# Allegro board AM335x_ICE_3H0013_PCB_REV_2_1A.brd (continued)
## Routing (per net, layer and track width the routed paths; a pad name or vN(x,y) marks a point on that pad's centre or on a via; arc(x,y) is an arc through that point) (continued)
GND_EARTH: length 5.8
  TOP w0.381: S1.3 v1(0.89,20.83)
  TOP w0.762: v2(2.37,5.39) 2.41,5.39 3.25,4.55 J13.S1 ; J13.S2 9.45,4.77 v2(8.89,5.33)
  BOTTOM w0.762: J16.11 29.09,13.59 28.84,13.84
  vias: v2(30.1,1.02)
GND_OSC0: length 16.1
  TOP w0.203: U14.V11 37.85,51.57 v1(37.85,53.34)
  LYR4 w0.381: v1(34.89,53.63) 35.6,53.63 35.74,53.77 37.16,53.77 37.59,53.34 v1(37.85,53.34) 38.22,53.72 38.22,53.73 40.87,56.37 v1(40.87,57.76)
  BOTTOM w0.381: v1(34.89,53.63) 35.46,54.19 35.46,55.41 35.1,55.77 35.04,55.77 C99.2 ; C100.2 40.89,57.74 v1(40.87,57.76) ; v1(37.85,53.34) 37.92,53.26 37.92,53.24 38.35,52.81 C106.2
GND_OSC1: length 13.5
  TOP w0.381: U14.A5 42.97,35.26 43.69,34.54 43.69,33.66 44.11,33.24 44.11,31.88 43.94,31.72 43.94,29.96 44.52,29.39 45.01,29.39 45.4,29.78 45.4,30.04 C40.1 45.91,30.23 v1(46.2,29.93) 46.2,29.01 45.59,28.4 C42.1
GNDA_ADC: length 77.7
  TOP w0.305: v1(40.97,40.45) U14.E8 ; v1(40.17,37.25) U14.A9
  TOP w0.381: C36.2 40.39,32.17 40.49,32.07 v1(40.49,31.65) ; C36.2 C35.2 C34.2 ; C36.2 40.89,32.77 41.15,33.02 41.15,34.8 40.17,35.78 v1(40.17,37.25) ; C34.2 C33.2 ; C34.2 38.35,32.19 v1(38.19,32.02)
  LYR3 w0.508: v2(71.1,31.82) 71,31.72 v2(71,30.76)
  LYR3 w0.635: v1(38.19,32.02) 38.1,31.93 38.1,31.22 39.28,30.05 40.06,30.05 40.49,30.48 v1(40.49,31.65) 40.78,31.94 41.67,31.94 42.68,30.94 43.42,30.94 45.67,28.69 46.45,27.9 46.45,27.89 47.07,27.27 60.96,27.27 61.6,27.9 63.04,27.9 63.88,27.06 65.79,27.06 66.74,28.01 68.25,28.01 v2(71,30.76)
  LYR4 w0.635: v2(71.1,31.82) 71.03,31.9 71.03,33.3 71.38,33.66 71.38,38.06 71.8,38.48 71.8,47.17 J14.38 J14.40
  BOTTOM w0.635: FB11.1 37.85,31.75 38.1,32 38.17,32 v1(38.19,32.02)
  BOTTOM w0.762: J14.39 J14.40
GNDPROFI: length 40.1
  TOP w0.635: v1(10.79,58.67) 11.7,59.58 L1.7 ; L1.6 v1(13.7,58.67) ; C24.2 22.35,53.72 21.99,53.36 21.23,53.36 v1(21.21,53.34) v1(20.45,53.34) ; U16.5 v2(5.84,45.09)
  LYR5_PWR w0.762: 16.76,39.12 16.76,40.01 16,40.01
  LYR5_PWR w0.889: 18.48,40.32 J8.3 18.48,41.47 ; 19.24,43.62 J7.2 19.24,44.77
  BOTTOM w0.508: C95.2 5.19,60.45 R153.1 8.13,60.45 8.26,60.33 ; v1(20.45,53.34) 20.45,52.47 C107.2 21.21,52.43 v1(21.21,53.34)
  BOTTOM w0.559: v1(8.26,58.67) 8.26,60.33 ; U28.11 v1(10.79,58.67) ; U28.15 15.88,58.93 v1(14.61,57.66) ; U28.14 v1(14.61,58.67) ; v1(20.45,53.34) 20.19,53.59 U27.4 ; 21.46,54.8 21.46,53.59 v1(21.21,53.34)
  BOTTOM w0.584: v1(11.16,36.02) C191.2 11.16,37.31 10.67,37.81 C185.2 v1(11.68,38.73) ; v1(6.6,49.78) R175.2
  BOTTOM w0.635: C98.2 v1(17.14,56.64) ; C96.2 4.05,60.56 C95.2
V3_3D: length 219.3
  TOP w0.254: U1.G4 v1(24.37,87.03) ; U11.16 45.2,62.11 C20.1 ; U9.16 34.02,65.04 C19.1 v1(34.8,65.02)
  TOP w0.305: v1(23.88,29.46) 23.63,29.71 U18.42 ; U18.31 20.27,22.5 v1(19.86,22.1) 18.92,22.1 18.77,22.25 U18.28 ; v2(32.64,74.55) C9.1 32.65,75.32 U2.32 ; v1(42.29,69.34) C15.1 41.49,69.39 U2.48 ; U18.56 17.27,33.61 17.2,33.54 17.16,33.54 16.9,33.27 v1(16.76,33.27) ; U18.20 v1(14.77,24.64) ; U3.48 57.87,71.29 58.55,70.61 C11.1 v1(59.31,69.98)
  TOP w0.381: R11.1 67.56,74.2 v2(67.31,74.46) ; C8.1 v1(72.9,72.09) ; U19.1 39.48,27.64 40.39,26.74 44.97,26.74 v2(45.09,26.61) ; U16.1 v2(18.03,37.47) ; SW1.C2 21.97,92.81 21.01,93.78 v2(20.7,93.78) ; U19.4 40.78,30.19 40.82,30.19 v1(41.36,30.73) ; v2(62.57,74.32) 62.56,74.32 62.54,74.3 R19.2 ; v2(64.14,68.71) 64.79,69.36 U10.5 v2(65.89,69.49) ; U7.5 47.39,67.32 C17.1 47.62,67.82 v2(47.12,68.33) ; U17.8 27.23,27.94 v1(27.66,28.37) ; 49.04,69.23 v1(49.8,69.23) ; 49.04,69.23 C12.1 ; 49.04,69.23 U5.5 ; R21.2 v1(47.24,74.17) ; v2(58.09,68.1) 57.99,68.2 57.91,68.2 57.78,68.33 R34.2 R33.2 R32.2 R31.2 54.36,68.21 53.97,67.82 53.97,67.79 v2(53.92,67.74) ; v2(45.72,73.41) 45.47,73.66 R18.2 ; v2(52.19,68.9) 52.62,68.9 53.01,68.52 53.15,68.52 R30.2 53.21,68.33 52.83,67.94 52.45,67.94 v2(52.2,68.2) ; v2(20.7,100.53) 20.7,101.42 21.08,101.81 SW1.C1 ; U4.8 68.91,75.48 68.9,75.49 68.9,75.63 C7.1 68.06,75.82 v1(67.98,75.9) ; U37.20 53.72,62.46 53.42,62.17 53.28,62.17 C277.1 53.09,61.59 53.47,61.21 v2(54.1,61.21) ; v1(72.85,66.56) 72.85,66.62 73.23,67.01 R25.2 ; R16.2 v2(48.01,76.96) ; U8.5 39.48,66.82 C18.1 39.5,66.93 39.37,67.06 39.37,67.33 v2(39.05,67.65) 39.11,67.65 39.11,67.57 38.48,68.21 R27.2 R28.2 R29.2 ; 6.22,63.12 v2(6.22,66.71) ; R15.2 v1(30.73,77.72) ; v2(49.53,75.91) 49.02,75.41 C10.1 49.28,75.06 49.78,75.06 50.05,75.32 U3.32 ; 50.29,17.65 50.04,17.4 50.04,17.14 v1(49.91,17.02) ; R24.2 v1(67.61,67.01)
  TOP w0.508: C20.1 v1(45.97,62.1)
  TOP w0.584: v1(13.34,52.58) 13.7,52.21 L1.3 ; L1.2 v1(11.7,52.58)
  LYR3 w0.381: v2(45.09,26.61) 45.14,26.66 45.14,27.96 43.05,30.05 42.31,30.05 41.62,30.73 v1(41.36,30.73)
  LYR4 w0.508: v2(59.99,19.61) 60.13,19.47 60.24,19.47 62.1,17.6 62.1,12.7 63.4,11.4 63.4,8.35 v2(60.44,5.39)
  LYR5_PWR w0.889: J3.1 5.77,72.72 ; J3.1 4.26,74.22 ; J3.1 5.77,74.22 ; J3.1 4.26,72.72
  BOTTOM w0.254: U26.18 19.92,74.99 19.01,74.99 19,75 16.95,75 C86.1 ; C88.1 16.93,70.57 U26.7 ; U26.31 28.36,74.97 C85.1 ; U26.42 27.65,70.57 C87.1
  BOTTOM w0.381: v2(37.14,78.94) 37.15,78.94 37.59,79.39 R129.2 ; v2(39.5,85.98) 39.62,85.85 39.8,85.85 40.01,85.64 C80.1 ; R97.2 v1(39.69,97.79) ; U38.20 46,56.66 C275.1 45.97,57.53 46.35,57.91 v2(46.99,57.91) ; C93.1 v2(6.22,66.71) ; v2(65.89,69.49) 65.86,69.47 65.15,69.47 ; C88.1 v1(16.13,70.61) ; R131.2 v1(30.73,77.72) ; C190.1 v2(18.03,37.47) ; v2(37.97,84.2) R123.1 R122.1 v2(40.58,84.77) 41.02,84.33 R121.1 R120.1 42.25,84.2 v2(42.8,84.75) ; R124.2 v2(53.85,84.33) ; R280.1 v1(60.01,96.14) ; v1(19.86,22.1) 20.27,22.5 20.27,22.55 C230.1 ; v2(54.61,84.33) R119.1 R118.1 ; J15.5 v1(72.9,72.09) ; v2(31.18,82.87) 31.18,83.77 R240.2 ; v2(60.02,85.22) 60.02,85.29 60.45,85.72 R114.1 ; R98.2 v1(40.96,97.79) ; v2(40.74,86.01) 41.02,85.73 C79.1 ; 43.81,87 v2(43.05,87) ; R94.2 v1(35.88,97.79) ; v1(24.37,87.03) 24.38,87.02 C75.1 C76.1 ; R118.1 C78.1 C77.1 57.59,85.66 57.59,85.8 57.71,85.92 57.72,85.92 v2(57.91,86.11) ; R118.1 R117.1 R116.1 v2(59.18,84.33) ; v2(18.03,98.21) C70.1 18.07,98.89 U25.8 ; J17.7 58.06,4.21 58.09,4.25 58.09,4.57 58.93,5.41 58.93,5.59 C266.1 ; R90.2 v1(57.47,97.79) ; R89.2 v1(56.2,97.79) ; C69.1 v2(20.7,100.53) ; R279.1 39.69,95.07 v1(39.69,96.14) ; R93.2 v1(61.28,97.79) ; v1(16.76,33.27) 17.02,33.53 C207.1 ; 64.14,69.47 v2(64.14,68.71) ; R111.2 v2(17.78,87.88) ; v1(4.57,24.13) 4.06,24.13 3.81,23.88 R211.2 C232.2 ; R92.2 v1(60.01,97.79) ; C86.1 v1(16.13,75.06) ; v2(62.99,77.6) R130.2 ; R101.2 v2(26.42,93.73) ; 29.59,82.93 v2(29.59,82.17) ; R95.2 v1(37.15,97.79) ; FB12.1 16.26,29.28 v1(16.26,30.11) 16.26,30.92 FB10.1 15.63,30.93 v1(15.63,30.11) 15.62,30.11 15.62,29.27 FB12.1
  BOTTOM w0.508: C219.1 R200.2 27.59,28.45 v1(27.66,28.37) ; R205.2 v1(11.94,24.64) ; v2(34.04,62.99) 34.04,63.88 33.77,64.15 C92.1 33.27,64.15 33.02,63.9 v2(33.02,62.99) ; C231.1 14.47,23.88 14.47,24.34 v1(14.77,24.64) ; v2(49.75,78.87) 49.73,78.86 R241.2 ; C85.1 v2(28.45,74.3) ; U31.1 61.09,21.72 60.71,21.34 C236.1 C238.1 60.17,19.3 59.99,19.48 v2(59.99,19.61) ; v1(9.91,21.34) 9.78,21.46 9.78,22.23 R210.2 9.08,22.35 9.02,22.29 U33.6 ; v2(38.88,59.9) 38.86,59.9 38.82,59.94 R145.2 ; v1(13.34,52.58) 13.34,49.15 C123.1 ; v2(44.2,62.87) 44.58,62.48 C94.1 45.58,61.71 v1(45.97,62.1) ; v1(7.11,26.42) 7.37,26.42 7.62,26.17 R206.2 ; R148.2 34.92,59.31 v2(35.01,59.23) ; v1(28.86,29.49) 28.98,29.49 30.02,28.45 R199.2 ; C87.1 v1(27.69,71.37) ; v1(41.36,30.73) 41.37,30.73 41.18,30.55 41.18,30.43 40.64,29.88 C218.1 ; R29.2 R28.2 39.05,67.88 v2(39.05,67.65) ; v1(23.88,29.46) C220.1 ; v2(60.44,5.39) 60.45,5.4 60.45,5.72 60.58,5.85 C265.1 C266.1 ; FB9.1 18.54,34.48 v1(18.54,33.27)
  vias: v2(61.98,27.05) v2(61.98,26.29) v2(61.98,25.53) v2(61.98,24.77) v2(62.74,26.29) v2(62.74,25.53) v2(62.74,24.77) v2(62.94,26.95) v2(66.62,54.7) v2(67.31,54.74)
V3_3D_PROFIA: length 5.1
  TOP w0.584: L1.4 15.7,52.02 16.26,52.58 v1(17.14,52.58)
  BOTTOM w0.635: v1(17.14,52.58) U28.1
V3_3D_PROFIB: length 11
  TOP w0.584: L1.1 9.7,52.5 10.79,53.59 v1(13.34,53.59)
  BOTTOM w0.508: v1(13.34,53.59) 14.99,53.59 15.88,52.7 U28.2
V3_3D_PRUETH0JCK: length 9.4
  BOTTOM w0.381: J2.4 59.37,89.61 J2.3 60.01,91.52 R280.2 ; R280.2 59.62,93.47 C72.1 ; R280.2 60.4,93.47 C71.1
V3_3D_PRUETH1JCK: length 9.5
  BOTTOM w0.381: R279.2 40.02,93.47 C73.1 ; R279.2 39.49,93.47 C74.1 ; R279.2 39.69,93.14 39.69,91.52 J1.3 39.05,89.61 J1.4
V5_0D: length 61
  TOP w0.203: 21.37,12.08 21.37,11.66 21.17,11.45 U22.47 ; v2(13.59,12.7) 14.08,12.7 14.68,12.1 U22.13 ; U22.41 21.46,9.05 ; v2(19.56,13.95) 19.53,13.95 19.05,13.47 U22.3 ; v2(17.53,13.92) 17.85,13.59 U22.6 ; U22.23 14.23,7.85 14.05,7.67 v2(13.64,7.67)
  TOP w0.254: 20.39,6.78 20.29,6.68 U22.36
  TOP w0.381: 21.46,9.05 23.28,9.05 v2(23.88,9.65) ; 21.37,12.08 21.37,13.78 v2(21.21,13.95)
  TOP w0.508: C61.1 v2(23.88,9.65) ; v2(19.56,13.95) 19.56,14.89 C58.1 ; v2(21.21,13.95) C59.1 ; v2(17.53,13.92) C57.1
  LYR3 w0.889: 75.07,36.69 J14.27 ; J14.27 76.57,36.69 ; J14.27 76.57,35.19 ; J14.27 75.07,35.19 ; 72.53,36.69 J14.28 ; J14.28 74.03,35.19 ; J14.28 72.53,35.19 ; J14.28 74.03,36.69
  LYR4 w0.508: v1(57.02,9.4) 59.31,9.4 v2(60.58,8.13)
  LYR4 w0.889: 72.53,36.69 J14.28 ; J14.28 74.03,35.19 ; J14.28 72.53,35.19 ; J14.28 74.03,36.69 ; 75.07,35.19 J14.27 ; J14.27 76.57,35.19 ; J14.27 76.57,36.69 ; J14.27 75.07,36.69
  BOTTOM w0.381: R224.1 v1(57.02,9.4)
  BOTTOM w0.508: C257.1 12.7,8.72 12.7,8.34 13.37,7.67 v2(13.64,7.67) ; R143.1 69.75,82.19 v2(70,82.44) ; R133.1 72.16,77.87 v2(72.41,78.12) ; v2(70,78.12) 69.75,77.87 R132.1 ; R136.1 74.57,77.87 v2(74.83,78.12) ; v2(13.59,12.7) C251.1 ; v2(77.24,82.44) 76.98,82.19 R173.1 ; R140.1 76.98,77.87 v2(77.24,78.12) ; R155.1 74.57,82.19 v2(74.83,82.44) ; v2(74.91,52.58) C97.1 v2(76.07,53.85) ; v2(72.41,82.44) 72.16,82.19 R151.1
  BOTTOM w0.635: v2(71.88,22.99) v2(71.88,21.97)
  BOTTOM w0.889: J14.28 74.03,36.69 ; J14.28 72.53,36.69 ; J14.28 74.03,35.19 ; J14.27 76.57,35.19 ; J14.27 75.07,35.19 ; J14.27 75.07,36.69 ; J14.27 76.57,36.69
  vias: v2(15.49,5.23) v2(16.24,5.57) v2(23.88,7.87) v2(31.14,22.15) v2(31.8,21.64) v2(32.36,22.2) v2(32.94,21.64) v2(47.12,23.11) v2(48.01,23.11) v2(48.77,23.11) v2(65.48,16.46) v2(66.42,18.54) v2(66.42,16.26) v2(67.31,17.93) v2(67.31,17.07) v2(71.16,7.63) v2(71.3,9.6) v2(71.3,8.84) v2(71.9,7.62) v2(72.19,9.6) v2(72.19,8.84) v2(74.33,9.58) v2(75.09,9.34)
V5_0VOP: length 7.8
  TOP w0.381: v1(52.83,19.05) C55.1 51.96,19.16 U20.5
  BOTTOM w0.381: C240.1 52.07,19.94 51.42,20.59 C234.1 ; C240.1 52.04,18.89 U35.15 ; C240.1 52.7,18.92 v1(52.83,19.05)
V13: length 6.6
  TOP w0.508: 62.48,8.13 62.48,6.14 62.46,6.12 62.46,4.34 62.97,3.84 v2(62.97,3.66)
  BOTTOM w0.203: J17.1 61.16,3.66
  BOTTOM w0.508: 61.16,3.66 v2(62.97,3.66)
  vias: v2(62.61,9.78) v2(62.61,8.89)
V24_0HVS: length 46.5
  TOP w0.381: R243.1 71.04,21.97 72.31,20.7 J14.16
  TOP w0.508: v2(44.76,19.68) U21.7 v2(41.91,19.68)
  LYR3 w0.635: J14.16 J14.14
  LYR3 w0.889: 72.53,3.67 J14.2 ; J14.2 74.03,3.67 ; J14.2 74.03,2.17 ; J14.2 72.53,2.17 ; J14.4 74.03,6.21 ; J14.4 72.53,4.71 ; J14.4 72.53,6.21 ; J14.4 74.03,4.71
  LYR4 w0.889: J14.4 74.03,6.21 ; J14.4 74.03,4.71 ; J14.4 72.53,6.21 ; J14.4 72.53,4.71 ; 72.53,3.67 J14.2 ; J14.2 74.03,3.67 ; J14.2 72.53,2.17 ; J14.2 74.03,2.17 ; 74.03,8.75 J14.6 74.03,7.25 ; J14.14 74.03,17.41 ; J14.14 74.03,18.91 ; J14.14 72.53,18.91 ; J14.14 72.53,17.41 ; J14.12 74.03,14.87 ; J14.12 74.03,16.37 ; J14.12 72.53,14.87 ; J14.12 72.53,16.37 ; J14.10 74.03,12.33 ; J14.10 74.03,13.83 ; J14.10 72.53,13.83 ; J14.10 72.53,12.33 ; J14.16 74.03,19.95 ; J14.16 72.53,19.95 ; J14.16 74.03,21.45 ; 74.03,11.29 J14.8 72.53,11.29
  vias: v2(45.62,20.22) v2(45.87,6.25) v2(46.65,20.22) v2(46.74,5.21) v2(70.84,4.76) v2(70.83,3.88) v2(70.81,2.91) v2(71.63,4.76) v2(71.62,3.88) v2(71.59,2.91)
V24_IN: length 25.1
  TOP w0.889: 35.01,11.22 J11.1 ; J11.1 38.4,11.22 ; J11.1 35.01,7.83 ; J11.1 38.4,7.83
  LYR3 w0.889: 35.01,11.22 J11.1 38.4,11.22
  LYR4 w0.889: 4.26,94.54 J3.17 5.77,94.54
  BOTTOM w0.889: 35.01,11.22 J11.1 35.01,7.83
  BOTTOM w1.27: J11.1 36.7,12.81 D18.2
  vias: v1(8.76,18.52) v2(8.76,20.07) v2(9.3,19.26) v2(9.66,20.08)
VBAT_LCD: length 3.8
  BOTTOM w0.381: C269.1 C268.1 57.02,5.97 57.02,5.72 56.56,5.26 J17.10
VDD1_SMPS:
  vias: v2(33.53,13.15) v2(33.71,14) v2(34.39,14.22) v2(34.39,12.95)
VDD1_SMPS_AM335X: length 47
  TOP w0.305: U14.J13 v1(36.17,43.65) U14.H13 36.45,43.13 36.45,42.57 U14.G13 v1(36.17,42.05) U14.F13 U14.F12 U14.F11 v1(38.57,42.05) U14.F10
  TOP w0.381: U14.A2 45.37,36.7 47.75,34.32 47.75,34.1 49.31,32.53 49.31,32.04 50.55,30.81 TP25.1 49.35,28.45 47.96,27.05 47.25,27.05 v2(46.23,26.04) ; v2(32.46,34.59) 32.5,34.56 v2(32.5,33.89) 32.73,33.66 33.04,33.66 33.46,33.23 33.46,33.08 C37.1
  LYR4 w0.762: 35.99,21.01 36.7,20.29 36.7,17.75 36.17,17.22 ; 35.99,21.01 40.82,25.83 43.77,25.83 43.9,25.97 44.62,25.97 44.77,25.82 46.01,25.82 v2(46.23,26.04) ; 35.99,21.01 35.45,21.55 34.28,21.55 33.73,22.1 33.73,22.63
  BOTTOM w0.254: v1(38.57,42.05) 38.15,41.63 38.15,41.47 37.82,41.14 C170.1
  BOTTOM w0.305: C151.1 36.28,43.76 v1(36.17,43.65)
  vias: v2(33.59,16.74) v2(33.56,15.8) v2(34.41,16.72) v2(34.5,15.74)
VDD2_SMPS: length 1.7
  BOTTOM w0.762: 30.63,18.98 R212.1 29.02,18.98 v2(28.96,18.92)
  vias: v2(28.9,19.9)
VDD2_SMPS_AM335X: length 25.4
  TOP w0.203: 42.17,41.63 U14.F6
  TOP w0.254: U14.G6 v1(41.77,42.05) U14.F6 ; v1(42.57,41.22) 42.17,41.63
  TOP w0.305: U14.L7 v1(40.97,45.25) 40.72,45 U14.K8 ; U14.M11 v1(38.57,46.05) ; U14.K6 v1(42.57,45.25) U14.L6 ; U14.H11 v1(38.57,42.85) U14.G10 ; U14.F7 v1(41.77,42.05) U14.G7 ; v1(40.97,46.05) U14.L8 ; U14.N9 v1(40.17,47.65) U14.N8 ; v1(40.17,46.05) U14.L9 ; U14.N13 v1(36.97,46.85) U14.N12 ; U14.M13 v1(36.17,46.85) ; U14.J12 v1(36.97,43.65) ; v1(36.97,45.25) U14.K12
  LYR4 w0.381: 29.46,38.99 30.23,38.23 v1(30.24,38.23)
  BOTTOM w0.203: v1(41.77,42.05) 41.39,41.67 41.39,41.52 41.01,41.14 C169.1
  BOTTOM w0.305: C149.1 40.46,44.74 v1(40.97,45.25) ; v1(40.17,47.65) 39.66,48.16 C130.1 ; v1(38.57,42.85) 38.68,42.74 39.34,42.74 C155.1 ; v1(36.17,46.85) 36.28,46.96 C131.1 ; v1(36.97,45.25) 37.26,44.96 37.26,44.48 C150.1 ; C134.1 v1(40.97,46.05) ; v1(40.17,46.05) 40.09,46.13 C142.1
  BOTTOM w0.381: v1(30.24,38.23) 30.35,38.23 30.53,38.05 31.17,38.05 C187.1 C192.1
  BOTTOM w0.508: C171.1 28.96,40.77 v2(28.96,40.64) 28.7,40.39 28.7,39.61 C178.1
  vias: v2(28.05,42.93) v2(28.82,43.02) v2(29.06,21.64) v2(34.34,18.96) v2(35.1,20.02) v2(35.05,19.3)
VDD_1V8FT: length 34.1
  TOP w0.305: U18.49 20.77,33.49 20.55,33.27 19.99,33.27 v1(19.91,33.2) ; 20.56,27.94 21.08,27.94 21.51,27.5 21.51,27.44 21.68,27.27 22.38,27.27 22.45,27.21 U18.37 23.59,27.21 v1(23.88,26.92) ; 13.27,33.09 U18.64 12.56,34.56 v1(12.45,34.67) ; U18.12 12.6,27.21 12.83,27.43 v1(12.83,27.94)
  TOP w0.381: 19.35,32.64 20.28,31.71 20.28,28.22 20.56,27.94 ; 19.35,32.64 17.79,32.64 17.46,32.31 14.05,32.31 ; 19.35,32.64 v1(19.91,33.2) ; v1(12.83,27.94) 13.72,28.83 13.72,31.98 14.05,32.31 ; 14.05,32.31 13.27,33.09
  BOTTOM w0.381: v1(12.45,34.67) 12.89,34.67 13.27,35.05 C208.2 ; C224.1 12.28,27.65 12.57,27.94 v1(12.83,27.94)
  BOTTOM w0.508: v1(23.88,26.92) 23.75,27.05 C225.2 ; v1(19.91,33.2) 20.09,33.38 21.56,33.38 22.1,33.91 C206.2
VDD_FTREGIN: length 2.6
  TOP w0.305: v1(20.32,35.81) 20.27,35.76 U18.50
  BOTTOM w0.508: v1(20.32,35.81) 20.32,34.73 FB9.2
VDD_FTVPHY: length 3.7
  TOP w0.305: U18.4 12.54,31.21 v1(12.83,31.5)
  BOTTOM w0.381: FB10.2 13.08,31.24 v1(12.83,31.5) C213.2
VDD_FTVPLL: length 3.6
  TOP w0.305: v1(12.83,28.96) 12.83,28.95 12.58,28.71 U18.9
  BOTTOM w0.381: FB12.2 v1(12.83,28.96) C221.2
VDD_LED: length 97.9
  TOP w0.305: R128.2 71.25,87.12 v2(70.83,87.54)
  TOP w0.508: C45.1 51.41,26.6 FB3.1
  TOP w0.635: v1(74.97,93.93) 75.03,93.93 75.53,94.44 D1.1 ; D2.1 75.71,89.48 74.83,88.61 v2(74.83,88.28) ; C45.1 52.87,28.07 52.87,30.12 50.82,32.17 50.82,33.07 49.07,34.82 49.07,44.08 56.93,51.94 58.17,51.94 60.11,53.89 63.28,53.89 63.88,54.48 v2(64.26,54.48)
  LYR3 w0.635: 66.55,55.63 67.94,55.63 68.94,56.62 68.94,59.41 70.57,61.05 72.54,61.05 73.03,61.54 73.03,63.51 73.57,64.05 73.57,75.03 73.03,75.56 71.75,75.56 71.29,75.1 70.92,75.1 70.91,75.1 70.31,75.1 69.89,75.52 69.89,75.8 68.44,77.25 68.44,85.86 70.12,87.54 v2(70.83,87.54) 74.1,87.54 v2(74.83,88.28) 74.83,93.79 v1(74.97,93.93)
  vias: v2(64.77,53.85) v2(65.66,53.85)
VDD_RTC: length 5.6
  TOP w0.305: v1(42.57,39.65) U14.D6
  BOTTOM w0.381: v1(42.57,39.65) 44.45,37.77 C195.1
VDDA_ADC: length 14.3
  TOP w0.305: v1(40.97,39.65) U14.D8
  TOP w0.381: C36.1 40.39,34.41 39.87,34.92 R60.2 39.4,34.92 39.48,35 v1(39.48,36.32)
  LYR3 w0.203: 39.62,39.24 39.74,39.36 39.74,39.83 39.99,40.08 40.35,40.08 40.65,39.78 40.84,39.78 v1(40.97,39.65)
  LYR3 w0.381: 39.62,39.24 39.22,38.84 39.22,36.58 v1(39.48,36.32) 39.48,33.63 39.62,33.48 v1(39.62,32.05) 39.62,32.04 39.59,32 39.51,32 39.05,31.55 v2(39.05,31.53)
VDDS_DDR: length 55.8
  TOP w0.254: v1(64.08,45.99) 64.07,45.99 63.73,45.65 U15.G7 ; C26.1 C25.1 52.91,52.96 52.6,53.27 v1(52.6,53.33) ; v1(56.95,39.2) 57,39.25 U15.R1 ; U15.B2 v1(59.3,49.25) ; v1(58.35,46.33) 58.79,46.33 U15.F1 ; v1(59.36,42.85) 59.36,42.91 U15.K2 ; U15.H9 v1(65.87,44.85) ; U15.D2 v1(59.3,47.65) ; v1(58.01,48.75) 58.8,48.75 U15.C1 ; U15.A8 v1(64.1,50.05) ; v1(43.37,40.45) U14.E5 43,40.85 v1(43.37,41.22) 42.97,41.63 U14.F5 U14.G5 U14.H5 ; U15.K8 v1(64.9,42.85) ; U15.N9 v1(65.7,40.45) ; U15.H2 v1(59.3,44.45) ; U15.R9 v1(65.87,39.25) ; U15.D9 v1(65.87,48.05) ; v1(57.79,41.02) 58.73,41.02 U15.N1 ; U15.C9 v1(65.87,48.85) ; U15.E9 v1(65.87,47.25) ; U15.A1 v1(58.9,51.02)
  TOP w0.305: U14.H5 v1(43.37,43.65) U14.J5 ; U14.L5 v1(43.37,45.25) U14.K5
  TOP w0.381: v1(52.91,35.81) 52.91,36.53 R59.1
  TOP w0.508: v2(68.04,31.31) 67.62,31.31 67.62,31.3 66.98,31.95 66.98,33.33 66.75,33.55 66.75,34.09 ; C27.1 v2(50.05,50.05) 49.4,50.05 v2(49.37,50.02) ; v2(52.32,37.96) C28.1 v2(49.77,37.96)
  BOTTOM w0.254: C180.1 66.08,39.04 v1(65.87,39.25) ; v1(56.52,41.53) 56.53,41.53 57.15,42.15 C162.2 ; v1(53.26,53.37) 52.64,53.37 v1(52.6,53.33) 52.6,52.96 52.86,52.7 C25.1 C26.1 ; v1(57.79,41.02) 57.59,40.82 C174.1 ; v1(65.87,48.85) 65.99,48.98 C122.1 ; C140.1 58.3,46.27 v1(58.35,46.33) ; U29.2 68.83,31.5 R191.2 ; v1(59.3,47.65) 59.39,47.74 C128.1 ; v1(65.87,47.25) 65.96,47.16 C136.1 ; v1(64.9,42.85) 64.98,42.93 C156.1 ; C146.1 59.39,44.54 v1(59.3,44.45) ; v1(65.87,48.05) 65.66,48.26 C127.1 ; v1(58.01,48.75) 57.95,48.69 C126.1 ; v1(65.87,44.85) 65.93,44.91 C144.1 ; C183.1 56.53,39.2 v1(56.95,39.2) ; v1(64.1,50.05) 64.11,50.04 C117.1 ; C176.1 65.71,40.44 v1(65.7,40.45) ; C118.1 59.44,49.78 59.3,49.65 v1(59.3,49.25) ; v1(58.9,51.02) 58.86,51.05 C115.1
  BOTTOM w0.381: R191.2 68.07,31.37 68.01,31.31 v2(68.04,31.31) 68.04,30.69 v2(67.97,30.62)
  BOTTOM w0.508: v2(57.17,52.98) 57.17,52.98 C101.1 59.99,52.98 v2(60.13,52.83) ; v2(49.55,33.15) C209.1 v2(48.39,34.42) ; v2(62.94,51.89) 63.59,51.89 64.02,52.32 C102.1 64.02,52.58 63.59,53.01 v2(62.94,53.01) ; v2(49.55,51.03) C104.1 49.55,52.32 v2(48.28,52.32)
  vias: v1(52.91,33.53) v2(7.6,6.3) v2(8.16,5.85) v2(8.77,6.17) v2(9.47,6.01)
AIN1: length 61.4
  TOP w0.121: v1(41.77,38.85) U14.C7
  LYR3 w0.127: v1(41.77,38.85) 41.77,38.77 42.01,38.53 42.01,38.05 42.47,37.59 42.95,37.59 50.11,30.43 56.78,30.43 57.69,31.34 58.62,31.34 58.86,31.58 61.83,31.58 62.59,32.35 64.88,32.35 66.17,33.63 66.17,35.46 67,36.3 67,36.6 68.44,38.05 68.44,45.15 72.88,49.59 76.21,49.59 76.77,49.04 76.77,41.97 J14.31
AIN2: length 54
  TOP w0.121: U14.B7 v1(40.97,38.05)
  LYR3 w0.127: J14.33 74.53,42.28 74.53,40.75 73.42,39.64 72.62,39.64 71.17,38.19 71.17,33.02 67.96,29.81 67.62,29.81 67.06,29.25 61.87,29.25 60.77,28.16 47.31,28.16 40.16,35.31 40.16,36.59 39.78,36.97 39.78,38.21 40.01,38.44 40.33,38.44 40.73,38.05 v1(40.97,38.05)
AIN3: length 49.7
  TOP w0.121: v1(41.37,36.89) 41.37,36.89 U14.A7
  LYR3 w0.127: J14.35 74.53,44.81 74.53,43.44 73.32,42.23 72.2,42.23 70.48,40.51 70.48,35.66 69.37,34.54 68.99,34.54 64.89,30.44 61.62,30.44 60.7,29.53 59.51,29.53 59.33,29.35 47.95,29.35 43.63,33.67 43.44,33.67 41.24,35.86 41.24,36.75 v1(41.37,36.89)
AIN4: length 51.1
  TOP w0.121: v1(40.97,38.85) U14.C8
  LYR3 w0.127: v1(40.97,38.85) 41.05,38.85 41.73,38.17 41.73,38.01 42.45,37.29 42.77,37.29 49.89,30.18 58.79,30.18 59.07,30.46 60.48,30.46 61.26,31.24 61.85,31.24 62.7,32.09 64.99,32.09 66.42,33.53 66.42,35.06 67.43,36.07 67.82,36.07 68.72,36.97 68.72,42.89 73.27,47.43 74.61,47.43 J14.37
AIN5: length 46.5
  TOP w0.121: v1(40.17,38.05) U14.B8
  LYR3 w0.127: J14.32 73.14,41.02 70.87,38.74 70.87,35.02 69.21,33.37 68.73,33.37 65.34,29.98 65.34,29.78 65.07,29.5 61.21,29.5 60.29,28.57 56.65,28.57 56.13,29.09 47.63,29.09 46.37,30.35 45.47,30.35 40.57,35.25 40.57,37.65 v1(40.17,38.05)
AIN6: length 45.5
  TOP w0.121: v1(40.96,37.27) 40.95,37.27 U14.A8
  LYR3 w0.127: v1(40.96,37.27) 41.2,37.27 41.2,37.28 41.53,37.28 44.08,34.73 44.08,34.27 48.75,29.6 59.17,29.6 59.36,29.79 60.61,29.79 61.51,30.7 62.16,30.7 63.05,31.58 65.65,31.58 67.03,32.96 67.03,34.29 67.3,34.57 67.69,34.57 69.4,36.28 69.4,40.83 72.13,43.56 J14.34
AIN7: length 48.8
  TOP w0.121: v1(40.17,38.85) U14.C9
  LYR3 w0.127: v1(40.17,38.85) 40.21,38.81 40.4,38.81 40.76,38.46 41.12,38.46 41.43,38.15 41.43,37.79 44.78,34.44 44.78,33.93 48.85,29.86 58.89,29.86 59.16,30.13 60.58,30.13 61.4,30.95 61.98,30.95 62.87,31.84 65.37,31.84 66.78,33.25 66.78,35.05 67.28,35.56 68.07,35.56 69.08,36.57 69.08,41.87 73.28,46.07 J14.36
AM335X_OSC0_IN: length 58.2
  TOP w0.121: U14.V10 38.96,51.26 38.96,51.61 38.58,52 38.58,54.25 38.73,54.4 38.73,54.98 v1(38.72,54.99)
  BOTTOM w0.121: R144.2 73.54,59.81 71.26,59.81 71.25,59.8 68.5,59.8 67.92,59.22 66.98,59.22 66.63,59.57 66.63,60.3 63.63,63.31 63.63,64.11 63.12,64.62 63.12,66.57 62.95,66.74 62.95,67.12 62.45,67.63 54.7,67.63 54.39,67.94 54.39,67.94 54.17,68.16 54.16,68.16 54.04,68.28 52.94,68.28 52.39,67.73 50.4,67.73 49.85,68.28 48.45,68.28 47.36,67.2 47.36,65.39 47.37,65.39 47.37,64.98 46.82,64.43 46.74,64.43 46.6,64.29 44.66,64.29 44.48,64.11 44.48,63.91 44.18,63.62 43.96,63.62 43.21,62.87 42.67,62.87 42.29,62.48 42.29,59.44 43.01,58.71 43.01,58.33 42.42,57.74 42.42,56.81 42.22,56.62 42.22,56.32 R172.2 C100.1 39.35,56.01 Y3.3 38.89,56.03 38.73,55.88 38.73,55.01 v1(38.72,54.99)
AM335X_REFCLK_RMII1: length 66.6
  TOP w0.121: v1(27,53.47) 26.35,52.82 26.35,46.65 25.62,45.92 25.62,45.04 25.68,44.98 25.68,43.92 25.43,43.67 25.43,42.69 25.86,42.27 26.98,42.27 27.47,42.75 27.47,43.2 27.75,43.49 29.7,43.49 29.87,43.32 30.67,43.32 30.73,43.25 U14.H18 ; R13.2 47.88,78.74 v1(46.86,78.74)
  LYR4 w0.127: v1(27,53.47) 27,54.41 26.38,55.03 26.38,66.76 27.15,67.52 27.15,68.51 29.12,70.48 29.12,78.65 29.68,79.21 32.07,79.21 33.29,80.43 45.17,80.43 v1(46.86,78.74)
AM335X_REFCLK_RMII2: length 56.4
  TOP w0.121: R12.2 31.9,79.14 v1(31.9,79.63) ; U14.H16 33.77,42.85 31.34,42.85 30.94,42.45 28.35,42.45 27.67,41.77 23.94,41.77 v1(23.04,42.67)
  BOTTOM w0.121: v1(23.04,42.67) 23.04,46.35 22.36,47.04 22.36,48.9 22.72,49.27 25.22,49.27 25.85,49.9 25.85,57.42 29.05,60.62 29.05,66.28 29.65,66.89 29.81,66.89 31.8,68.88 31.8,70.74 31.53,71.01 31.53,72.81 31.33,73.01 31.33,74.89 32.27,75.82 32.27,79.26 v1(31.9,79.63)
B_PRUETH0_LINKLED: length 51
  TOP w0.121: v1(52.07,77.35) 52.04,77.32 U3.28
  LYR3 w0.127: v1(52.07,77.35) 52.07,77.58 50.83,78.81 50.83,84.02 52.51,85.7 52.51,91.15 52.51,91.47 52.73,91.7 52.73,91.77 55.78,94.81 55.78,100.23 56.77,101.22 v1(57.47,101.22)
  LYR4 w0.127: v1(52.07,77.35) 53.17,77.35 53.4,77.13 61.51,77.13 62.61,78.23 65.79,78.23 TP20.1
  BOTTOM w0.121: J2.10 56.89,101.8 v1(57.47,101.22) R90.1
BOOT: length 3.4
  TOP w0.635: U21.1 46.97,18.41 46.23,17.68 C56.1
C1N: length 4.7
  BOTTOM w0.121: J17.11 56.06,4.06 55.94,4.19 55.94,4.63 55.12,5.45 54.46,5.45 54.22,5.69 54.22,6.37 54.33,6.48 54.48,6.48 C270.2
C1P: length 5.1
  BOTTOM w0.121: J17.12 55.56,4 55.69,4.13 55.69,4.53 55.01,5.21 54.36,5.21 53.98,5.59 53.98,6.48 54.22,6.72 54.48,6.72 C270.1
C2N: length 5.1
  BOTTOM w0.121: C271.2 52.76,6.68 53.01,6.68 53.09,6.6 53.59,6.1 53.59,5.89 53.59,5.89 53.59,5.2 53.98,4.82 54.62,4.82 54.94,4.51 54.94,4.06 55.06,3.94 J17.13
C2P: length 4.7
  BOTTOM w0.121: C271.1 52.66,6.43 52.91,6.43 53.35,5.99 53.35,5.1 53.87,4.57 54.52,4.57 54.69,4.4 54.69,4.06 54.56,3.94 J17.14
CAN0_H: length 6.8
  TOP w0.121: U16.7 v1(5.84,40.01) 4.83,40.01 4.08,39.26 J9.7
  BOTTOM w0.121: R238.1 v1(5.84,40.01)
CAN0_L: length 12.6
  TOP w0.121: J9.2 4.47,37.87 5.4,38.8 7.56,38.8 v1(7.75,38.99) 7.87,39.12 8.38,39.12 9.02,39.75 9.02,42.3 8.77,42.55 U16.6
  BOTTOM w0.121: R238.2 v1(7.75,38.99)
CAN0_RXDF: length 2.8
  TOP w0.121: U16.2 v1(14.73,40.01)
  BOTTOM w0.121: v1(14.73,40.01) R186.2
CAN0_TXDF: length 5.6
  TOP w0.121: U16.3 14.86,42.55 14.1,43.31 v1(14.1,43.81)
  BOTTOM w0.121: v1(14.1,43.81) 15.11,43.81 R181.2 C145.1
CAN_GND/PROFIBUS_A: length 19.2
  TOP w0.584: v1(5.84,41.27) 4.83,41.27 4.19,40.64 J9.3
  BOTTOM w0.584: J8.2 19.98,41.24 19.98,41.28 19.32,41.94 8.28,41.94 7.62,41.27 v1(5.84,41.27)
CAP_VBB_MPU: length 4.7
  TOP w0.254: U14.C10 38.58,38.86 v1(38.57,38.85)
  BOTTOM w0.381: C199.1 40.13,35.56 40.13,36.46 39.33,37.25 39.33,37.88 38.76,38.46 38.76,38.66 v1(38.57,38.85)
CAP_VDD_SRAM_CORE: length 5.2
  TOP w0.254: v1(40.17,39.65) U14.D9
  BOTTOM w0.127: 40.57,39.25 40.57,37.03 40.85,36.75
  BOTTOM w0.203: v1(40.17,39.65) 40.57,39.25
  BOTTOM w0.381: 40.85,36.75 40.85,36.03 41.27,35.6 C198.1
CAP_VDD_SRAM_MPU: length 5.4
  TOP w0.254: v1(37.77,39.65) U14.D11
  BOTTOM w0.127: 38.18,39.14 38.18,38.36 38.28,38.26
  BOTTOM w0.254: 38.18,39.14 38.18,39.24 v1(37.77,39.65)
  BOTTOM w0.381: 38.28,38.26 38.4,38.13 38.4,36.45 39.24,35.61 C200.1
DDR_A0: length 32.1
  TOP w0.121: U15.N3 v1(61.78,40.85) ; U14.F3 v1(44.97,41.25)
  LYR3 w0.127: v1(61.78,40.85) 61.78,41.87 61.67,41.99 60.92,41.99 60.82,41.88 60.82,41.47 60.7,41.36 60.55,41.36 60.43,41.47 60.43,41.86 60.23,42.07 57.21,42.07 56.94,42.34 56.94,42.78 56.82,42.91 56.57,42.91 56.44,42.78 56.44,42.21 56.29,42.06 56.1,42.06 55.99,42.17 55.99,42.78 55.88,42.89 55.67,42.89 55.56,42.78 55.56,42.17 55.45,42.06 55.26,42.06 55.15,42.17 55.15,42.78 55.04,42.89 54.81,42.89 54.7,42.78 54.7,42.17 54.58,42.06 54.41,42.06 54.24,42.23 54.24,42.56 54.1,42.7 48.73,42.7 48.46,42.96 47.02,42.96 46.73,43.25 46.4,43.25 46.16,43.01 46.16,42.69 45.92,42.44 45.61,42.44 45.38,42.21 45.38,41.9 44.97,41.49 v1(44.97,41.25)
  BOTTOM w0.121: RP2.1 62.26,36.81 62.09,36.97 61.72,36.97 61.64,37.05 61.64,37.49 61.95,37.8 61.95,38.73 61.92,38.77 61.76,38.93 61.76,40.82 v1(61.78,40.85)
DDR_A1: length 32.1
  TOP w0.121: U14.H1 v1(46.57,42.85) ; v1(62.38,40.01) 61.99,40.01 61.85,39.87 61.85,39.65 61.97,39.54 62.74,39.54 63,39.79 63.45,39.79 U15.P7
  LYR3 w0.127: v1(46.57,42.85) 47.13,42.29 47.83,42.29 47.97,42.15 48.3,42.15 48.44,42.29 49.93,42.29 50.05,42.18 50.05,41.79 50.16,41.68 50.31,41.68 50.43,41.79 50.43,42.18 50.54,42.29 50.7,42.29 50.81,42.18 50.81,41.79 50.92,41.68 51.08,41.68 51.19,41.79 51.19,42.18 51.3,42.29 51.46,42.29 51.57,42.18 51.57,41.79 51.68,41.68 51.84,41.68 51.95,41.79 51.95,42.18 52.06,42.29 52.22,42.29 52.33,42.18 52.33,41.79 52.44,41.68 52.6,41.68 52.71,41.79 52.71,42.18 52.82,42.29 52.98,42.29 53.09,42.18 53.09,41.79 53.2,41.68 53.36,41.68 53.47,41.79 53.47,42.18 53.59,42.29 53.74,42.29 53.86,42.18 53.86,41.79 53.97,41.68 55.77,41.68 56.41,41.04 57.22,41.04 57.71,40.55 58.65,40.55 58.95,40.86 59.47,40.86 60.54,40.86 60.71,40.69 60.71,39.93 61.11,39.52 62.71,39.52 62.88,39.69 62.88,39.86 62.73,40.01 v1(62.38,40.01)
  BOTTOM w0.121: v1(62.38,40.01) 62.38,39.75 62.67,39.46 62.67,38.34 62.88,38.14 63.18,38.14 63.36,37.96 63.36,37.58 63.26,37.48 RP2.3
DDR_A2: length 32.5
  TOP w0.121: U15.P3 v1(61.14,40.05) ; U14.E4 v1(44.17,40.45)
  LYR3 w0.127: v1(61.14,40.05) 61.55,40.46 61.95,40.46 62.18,40.69 62.18,41.06 62.32,41.2 63.2,41.2 63.38,41.38 63.38,41.56 63.16,41.78 62.74,41.78 62.53,41.99 62.52,41.99 62.17,42.34 57.85,42.34 57.53,42.66 57.53,42.98 57.2,43.31 46.99,43.31 46.82,43.48 46.31,43.48 46.08,43.26 45.62,43.26 45.36,43 45.36,42.69 45.12,42.44 44.81,42.44 44.58,42.21 44.58,40.56 44.47,40.45 v1(44.17,40.45)
  BOTTOM w0.121: RP3.7 60.69,36.87 60.86,37.04 60.86,39.5 60.4,39.96 60.4,40.29 60.73,40.62 60.97,40.62 61.14,40.45 v1(61.14,40.05)
DDR_A3: length 30.5
  TOP w0.121: U15.N2 59.42,40.85 59.28,40.72 59.28,40.58 59.4,40.46 59.92,40.46 60.1,40.65 v1(60.1,41.25) ; v1(44.97,38.85) U14.C3
  LYR4 w0.127: v1(60.1,41.25) 60.1,41.03 59.95,40.87 59.48,40.87 59.11,40.5 58.78,40.5 58.67,40.61 58.67,41.47 58.56,41.58 58.4,41.58 58.29,41.47 58.29,40.61 58.18,40.5 57.36,40.5 57.27,40.59 57.27,41.18 57.16,41.29 57.03,41.29 56.92,41.18 56.92,40.67 56.8,40.55 55.19,40.55 55.08,40.66 55.08,41.16 54.97,41.27 54.81,41.27 54.7,41.16 54.7,40.66 54.59,40.55 54.43,40.55 54.32,40.66 54.32,41.16 54.21,41.27 54.05,41.27 53.94,41.16 53.94,40.66 53.83,40.55 51.67,40.55 51,39.88 47.02,39.88 46.85,40.04 45.61,40.04 45.38,39.81 45.38,39.49 45.38,39.48 45.38,39.26 v1(44.97,38.85)
  BOTTOM w0.121: RP3.4 59.13,36.42 59.13,37.68 58.91,37.89 58.91,38.21 59.45,38.75 59.45,40.13 60.1,40.78 v1(60.1,41.25)
DDR_A4: length 33.7
  TOP w0.121: U15.P8 v1(64.1,39.65) ; U14.C2 v1(45.77,38.85)
  LYR3 w0.127: v1(45.77,38.85) 45.95,38.67 46.03,38.67 46.26,38.44 46.84,38.44 47.05,38.23 47.05,37.76 47.79,37.02 49.17,37.02 49.28,36.91 49.28,36.73 49.39,36.62 49.55,36.62 49.66,36.73 49.66,36.91 49.77,37.02 49.93,37.02 50.04,36.91 50.04,36.73 50.15,36.62 50.31,36.62 50.42,36.73 50.42,36.91 50.53,37.02 50.69,37.02 50.8,36.91 50.8,36.73 50.91,36.62 51.07,36.62 51.18,36.73 51.18,36.91 51.29,37.02 51.45,37.02 51.56,36.91 51.56,36.73 51.68,36.62 51.83,36.62 51.94,36.73 51.94,36.91 52.06,37.02 52.58,37.02 52.69,36.91 52.69,36.78 52.8,36.67 52.96,36.67 53.07,36.78 53.07,37.26 53.18,37.38 53.34,37.38 53.45,37.26 53.45,36.78 53.56,36.67 53.72,36.67 53.83,36.78 53.83,37.26 53.94,37.38 54.1,37.38 54.21,37.26 54.21,36.78 54.33,36.67 54.48,36.67 54.6,36.78 54.6,36.91 54.71,37.02 55.24,37.02 55.99,36.27 61.69,36.27 62.45,37.03 62.45,37.98 62.92,38.45 63.14,38.45 63.71,39.02 63.71,39.26 v1(64.1,39.65)
  BOTTOM w0.121: RP2.6 64.75,36.37 64.75,36.8 64.88,36.93 65.5,36.93 65.57,37 65.57,37.23 65.51,37.29 64.85,37.29 64.8,37.34 64.8,37.58 64.86,37.64 65.34,37.64 65.46,37.76 65.46,38.29 v1(64.1,39.65)
DDR_A5: length 30.6
  TOP w0.121: U14.B1 v1(46.57,38.05) ; v1(60.1,39.65) 60.08,39.62 59.36,39.62 59.28,39.7 59.28,39.93 59.4,40.05 U15.P2
  LYR4 w0.127: v1(46.57,38.05) 47.14,38.05 47.26,37.94 47.26,37.4 47.37,37.29 47.53,37.29 47.64,37.4 47.64,37.94 47.75,38.05 47.91,38.05 48.02,37.94 48.02,37.4 48.13,37.29 48.29,37.29 48.4,37.4 48.4,37.94 48.51,38.05 48.97,38.05 49.15,37.87 49.15,37.52 49.28,37.39 49.86,37.39 50.39,37.92 50.58,37.92 51.62,37.92 52.13,38.43 52.52,38.43 52.77,38.18 53.02,38.18 53.14,38.06 53.14,37.81 53.18,37.76 53.47,37.76 53.52,37.81 53.52,38.06 53.63,38.18 53.79,38.18 53.9,38.06 53.9,37.81 54.01,37.69 54.17,37.69 54.28,37.81 54.28,38.06 54.39,38.18 54.55,38.18 54.66,38.06 54.66,37.81 54.77,37.69 54.93,37.69 55.04,37.81 55.04,38.06 55.15,38.18 55.31,38.18 55.42,38.06 55.42,37.81 55.53,37.69 55.69,37.69 55.8,37.81 55.8,38.06 55.91,38.18 56.07,38.18 56.18,38.06 56.18,37.81 56.29,37.69 56.45,37.69 56.56,37.81 56.56,38.06 56.65,38.15 56.9,38.15 57.01,38.04 57.01,37.81 57.12,37.69 57.28,37.69 57.39,37.81 57.39,38.04 57.51,38.15 58.52,38.15 59.21,38.84 59.56,38.84 59.94,38.46 60.4,38.46 60.68,38.73 60.68,39.45 60.48,39.65 v1(60.1,39.65)
  BOTTOM w0.121: RP3.6 60.06,36.49 60.06,36.76 59.93,36.89 59.93,37.39 60.12,37.58 60.49,37.58 60.56,37.64 60.56,37.93 60.42,38.06 60.15,38.06 60.03,38.18 60.03,38.33 60.16,38.46 60.42,38.46 60.56,38.6 60.56,39.2 v1(60.1,39.65)
DDR_A6: length 34.3
  TOP w0.121: U15.R8 v1(64.1,38.85) 64.1,36.19 64.23,36.07 64.82,36.07 65.01,35.88 65.01,34.8 64.91,34.7 63.63,34.7 63.48,34.55 RP1.2 ; v1(43.37,39.65) U14.D5
  LYR3 w0.127: v1(43.37,39.65) 43.37,38.8 46.96,35.22 52.91,35.22 53.43,35.74 54.69,35.74 54.92,35.51 62.46,35.51 64.1,37.15 v1(64.1,38.85)
DDR_A7: length 34.4
  TOP w0.121: U14.E2 v1(45.77,40.45) ; RP1.8 60.48,34.2 60.31,34.36 59.29,34.36 58.99,34.66 58.99,37.29 59.3,37.6 59.91,37.6 60.1,37.79 v1(60.1,38.85) U15.R2
  LYR3 w0.127: v1(45.77,40.45) 45.77,40.21 46.16,39.81 46.16,39.5 46.41,39.26 47.17,39.26 47.51,38.92 47.71,38.92 47.82,39.03 47.82,39.51 47.93,39.62 48.09,39.62 48.2,39.51 48.2,39.03 48.28,38.96 53.45,38.96 53.56,38.84 53.56,38.41 53.67,38.3 53.83,38.3 53.94,38.41 53.94,38.84 54.05,38.96 55,38.96 56.9,37.05 58.02,37.05 58.13,37.16 58.13,37.51 58.24,37.62 58.4,37.62 58.51,37.51 58.51,37.16 58.62,37.05 58.78,37.05 58.89,37.16 58.89,37.51 59,37.62 59.16,37.62 59.27,37.51 59.27,37.16 59.38,37.05 59.72,37.05 59.81,37.14 59.81,38.33 59.92,38.44 60.08,38.44 60.2,38.32 60.2,37.71 60.3,37.6 60.55,37.6 61,37.15 61.01,37.16 61.31,37.16 61.46,37.31 61.46,37.5 61.47,37.5 61.47,37.8 60.95,38.32 60.95,38.47 60.57,38.85 v1(60.1,38.85)
DDR_A8: length 33.2
  TOP w0.121: U15.T8 v1(64.9,38.05) 65.17,38.05 65.4,37.81 65.4,37.62 65.3,37.51 64.94,37.51 64.83,37.4 64.83,37.25 64.94,37.15 65.3,37.15 65.4,37.04 65.4,36.89 65.3,36.79 64.94,36.79 64.83,36.68 64.83,36.53 64.94,36.42 65.3,36.42 65.4,36.32 65.4,34.63 65.06,34.28 64.36,34.28 63.98,33.9 RP1.1 ; v1(44.17,39.65) U14.D4
  LYR4 w0.127: v1(44.17,39.65) 44.17,39.42 43.78,39.02 43.78,38.69 44.14,38.32 44.14,38 45.92,36.22 51.55,36.22 51.95,36.61 53.24,36.61 53.31,36.55 59.07,36.55 60.09,37.58 60.54,37.58 60.77,37.35 64.2,37.35 v1(64.9,38.05)
DDR_A9: length 34.4
  TOP w0.121: RP1.6 61.48,34.99 61.27,35.2 60.15,35.2 59.99,35.36 59.99,36.09 60.13,36.23 61.21,36.23 61.48,36.5 61.48,38.34 v1(61.34,38.48) 60.57,39.25 U15.R3 ; U14.C1 v1(46.57,38.85)
  LYR3 w0.127: v1(61.34,38.48) 61.84,37.98 61.84,37.15 61.37,36.67 56.47,36.67 55.38,37.76 53.31,37.76 53.07,37.99 53.07,38.25 52.9,38.43 51.79,38.43 51.67,38.32 51.67,37.52 51.57,37.41 51.41,37.41 51.29,37.53 51.29,38.32 51.18,38.43 51.02,38.43 50.91,38.32 50.91,37.52 50.81,37.41 50.65,37.41 50.53,37.53 50.53,38.32 50.42,38.43 49.01,38.43 48.9,38.32 48.9,37.51 48.79,37.4 48.63,37.4 48.52,37.51 48.52,38.32 48.41,38.43 48.25,38.43 48.14,38.32 48.14,37.51 48.03,37.4 47.87,37.4 47.76,37.51 47.76,38.32 47.64,38.43 47.41,38.43 46.99,38.85 v1(46.57,38.85)
DDR_A10: length 37.8
  TOP w0.121: v1(62.72,42.35) 62.82,42.45 U15.L7 63.7,42.39 62.52,41.21 62.49,41.21 62.24,40.96 62.24,40.53 61.94,40.23 61.9,40.23 61.56,39.89 61.56,38.82 61.65,38.72 61.65,38.72 61.98,38.39 RP1.5 ; U14.F4 v1(44.17,41.25)
  LYR3 w0.127: v1(62.72,42.35) 62.95,42.12 64.28,42.12 64.41,42.25 64.41,42.69 64.24,42.86 60.98,42.86 60.59,43.24 58.7,43.24 58.23,43.71 45.54,43.71 45.11,44.14 44.72,44.14 44.58,43.99 44.58,42.7 44.32,42.44 44.01,42.44 43.78,42.21 43.78,41.89 44.17,41.49 v1(44.17,41.25)
DDR_A11: length 35.7
  TOP w0.121: U14.F2 v1(45.77,41.25) ; RP1.4 62.48,35.98 62.59,36.08 63.06,36.08 63.16,36.19 63.16,36.34 63.06,36.45 62.59,36.45 62.48,36.55 62.48,36.7 62.59,36.81 63.06,36.81 63.16,36.91 63.16,37.06 63.06,37.17 62.59,37.17 62.48,37.28 62.48,37.98 62.75,38.26 63.03,38.26 63.7,38.93 U15.R7 63.62,39.25 62.98,38.61 62.08,38.61 61.87,38.81 61.87,39 62.13,39.25 v1(63.06,39.25)
  LYR3 w0.127: v1(45.77,41.25) 45.77,41.27 46.15,41.66 46.95,41.66 47.3,41.3 47.48,41.3 47.59,41.41 47.59,41.75 47.7,41.86 47.86,41.86 47.97,41.75 47.97,41.35 48.09,41.24 48.24,41.24 48.35,41.35 48.35,41.75 48.47,41.86 48.62,41.86 48.74,41.75 48.74,41.35 48.85,41.24 49.01,41.24 49.12,41.35 49.12,41.75 49.23,41.86 49.39,41.86 49.5,41.75 49.5,41.41 49.61,41.3 55.27,41.3 55.97,40.6 56.78,40.6 57.15,40.24 57.15,39.91 57.49,39.57 59.38,39.57 59.49,39.68 59.49,40.36 59.6,40.47 60.29,40.47 60.4,40.36 60.4,39.91 61.06,39.25 v1(63.06,39.25)
DDR_A12: length 31.1
  TOP w0.121: v1(62.87,40.81) 62.91,40.85 U15.N7 ; v1(44.97,40.45) U14.E3
  LYR4 w0.127: v1(62.87,40.81) 62.78,40.72 62.78,39.52 62.66,39.41 62.66,38.84 61.63,37.81 59.7,37.81 58.82,36.93 53.47,36.93 53.4,37 51.79,37 51.42,36.63 45.84,36.63 44.58,37.89 44.58,39.01 44.97,39.41 v1(44.97,40.45)
  BOTTOM w0.121: RP2.4 63.76,37.24 64.02,37.51 64.02,38.01 63.85,38.17 63.69,38.17 63.45,38.41 63.45,39.54 62.63,40.36 62.63,40.57 v1(62.87,40.81)
DDR_A13: length 32.7
  TOP w0.121: U14.H3 v1(44.97,42.85) ; U15.T3 60.5,38.1 60.38,37.97 v1(60.38,37.19) 60.89,37.19 60.98,37.09 60.98,36.76 60.87,36.65 59.51,36.65 59.37,36.51 59.37,35.04 59.58,34.82 60.76,34.82 60.98,34.6 RP1.7
  LYR4 w0.127: v1(44.97,42.85) 44.57,42.45 44.57,41.89 44.32,41.64 44.01,41.64 43.76,41.4 43.76,39.49 43.55,39.27 43.55,38.42 43.75,38.21 43.75,38.03 45.97,35.81 51.68,35.81 52.1,36.23 53.09,36.23 53.15,36.17 59.36,36.17 v1(60.38,37.19)
DDR_A14: length 34.9
  TOP w0.121: RP1.3 62.98,34.9 63.16,35.09 64.5,35.09 64.63,35.21 64.63,35.36 64.5,35.49 63.89,35.49 63.73,35.65 63.73,37.56 63.67,37.62 63.09,37.62 v1(62.97,37.74) 63,37.74 U15.T7 ; U14.H4 v1(44.17,42.85)
  LYR3 w0.127: v1(62.97,37.74) 62.97,36.83 62.02,35.89 55.45,35.89 55.09,36.24 51.83,36.24 51.64,36.05 49.46,36.05 49.12,36.39 47.52,36.39 46.37,37.54 45.72,37.54 45.36,37.9 45.36,39.41 44.71,40.06 44.01,40.06 43.78,40.29 43.78,41.49 43.55,41.72 43.55,42.31 44.09,42.85 v1(44.17,42.85)
DDR_BA0: length 30.6
  TOP w0.121: U15.M2 v1(59.3,41.25) ; U14.C4 v1(44.17,38.85)
  LYR4 w0.127: v1(44.17,38.85) 44.28,38.96 44.28,39.2 44.56,39.49 44.56,41.4 44.81,41.64 45.22,41.64 45.36,41.5 45.36,41 45.52,40.84 45.61,40.84 46.99,40.84 47.14,40.69 47.14,40.46 47.29,40.31 47.55,40.31 47.73,40.49 47.73,40.72 47.88,40.87 48.23,40.87 48.75,40.36 50.8,40.36 51.38,40.94 53.42,40.94 53.56,41.09 53.56,41.54 53.72,41.71 55.4,41.71 55.55,41.55 55.55,41.08 55.69,40.94 55.88,40.94 56.06,41.12 56.06,41.94 56.18,42.06 58.93,42.06 59.21,42.34 59.77,42.34 60.05,42.06 60.05,41.78 59.92,41.66 59.44,41.66 59.3,41.52 v1(59.3,41.25)
  BOTTOM w0.121: RP3.3 58.75,36.42 58.75,37.45 58.47,37.73 58.47,38.27 59.12,38.91 59.12,40.19 59.63,40.71 59.63,40.92 v1(59.3,41.25)
DDR_BA1: length 33.6
  TOP w0.121: U14.E1 v1(46.57,40.45) ; U15.N8 64.12,40.47 63.36,40.47 v1(63.22,40.33)
  LYR3 w0.127: v1(46.57,40.45) 46.9,40.78 54.65,40.78 55.08,40.35 55.08,40.31 57.24,38.15 57.71,38.15 58.8,39.24 60.65,39.24 61.02,38.87 62.88,38.87 62.9,38.86 63.23,38.86 63.46,39.09 63.46,39.69 63.9,40.14 65.11,40.14 65.31,40.34 65.31,41.58 65.11,41.78 64.61,41.78 64.29,41.47 64.29,41.06 64.1,40.86 63.74,40.86 v1(63.22,40.33)
  BOTTOM w0.121: RP2.5 64.26,37.33 64.45,37.52 64.45,38.35 64.34,38.46 63.94,38.46 63.71,38.69 63.71,39.81 63.94,40.04 63.94,40.46 63.83,40.57 63.45,40.57 v1(63.22,40.33)
DDR_BA2: length 30.6
  TOP w0.121: v1(44.97,38.05) U14.B3 ; v1(61.21,41.4) 61.49,41.4 61.62,41.53 61.62,41.83 61.47,41.99 60.63,41.99 60.5,41.86 U15.M3
  LYR4 w0.127: v1(61.21,41.4) 61.21,40.77 61.67,40.31 61.67,39.07 61.48,38.88 61.2,38.88 61.04,39.04 61.04,39.6 60.59,40.04 59.94,40.04 59.71,39.81 59.71,39.6 59.51,39.4 58.93,39.4 58.75,39.22 58.75,38.83 58.42,38.51 58.04,38.51 57.94,38.61 57.94,38.81 57.81,38.94 57.24,38.94 56.9,38.6 55.36,38.6 55.07,38.89 54.81,38.89 54.48,38.56 53.11,38.56 52.73,38.93 51.92,38.93 51.44,38.46 45.38,38.46 v1(44.97,38.05)
  BOTTOM w0.121: RP3.8 61.27,36.44 61.27,37.85 61.73,38.32 61.73,38.64 61.53,38.84 61.53,40.46 61.21,40.78 v1(61.21,41.4)
DDR_CASN: length 32
  TOP w0.121: U15.K3 60.12,42.87 60.07,42.87 v1(60.07,42.85) ; U14.F1 v1(46.57,41.25)
  LYR4 w0.127: v1(60.07,42.85) 60.05,42.88 60.05,43.57 59.89,43.72 59.24,43.72 58.97,43.45 58.97,42.66 58.65,42.34 57.28,42.34 57.03,42.59 55.93,42.59 55.83,42.49 55.83,42.24 55.68,42.09 55.44,42.09 55.34,42.19 55.34,42.5 55.23,42.61 54.98,42.61 54.88,42.5 54.88,42.22 54.75,42.1 54.59,42.1 54.5,42.2 54.5,42.5 54.38,42.61 54.23,42.61 54.11,42.5 54.11,42.22 53.98,42.09 53.4,42.09 53.18,41.87 53.18,41.48 53.05,41.35 52.07,41.35 51.97,41.45 51.97,41.88 51.86,42 51.7,42 51.59,41.88 51.59,41.41 51.5,41.33 51.3,41.33 51.21,41.41 51.21,41.88 51.1,42 50.94,42 50.83,41.88 50.83,41.45 50.74,41.36 50.74,41.35 50.6,41.21 50.6,40.84 50.5,40.74 50.32,40.74 50.22,40.84 50.22,41.55 50.11,41.67 49.95,41.67 49.84,41.55 49.84,40.83 49.75,40.74 49.55,40.74 49.46,40.83 49.46,41.54 49.35,41.66 49.19,41.66 49.08,41.54 49.08,40.95 48.96,40.84 48.81,40.84 48.48,41.17 46.65,41.17 v1(46.57,41.25)
  BOTTOM w0.121: v1(60.07,42.85) 60.49,42.43 60.49,40.76 59.69,39.96 59.69,37.63 59.54,37.48 59.54,36.5 RP3.5
DDR_CKE: length 27.3
  TOP w0.121: U14.G3 v1(44.97,42.05) ; v1(65.91,43.51) 65.65,43.25 U15.K9
  LYR4 w0.127: v1(44.97,42.05) 45.37,42.45 45.37,43.01 45.61,43.24 49.57,43.24 50.07,43.74 53.09,43.74 53.89,44.54 57.4,44.54 57.6,44.74 58.45,44.74 59.14,44.06 60.86,44.06 61.2,43.72 61.77,43.72 62.4,44.35 62.61,44.35 63.1,44.84 65.07,44.84 65.3,44.61 65.3,44.13 v1(65.91,43.51)
  BOTTOM w0.121: R178.2 66.42,44.32 65.91,43.81 v1(65.91,43.51)
DDR_CLK: length 31.4
  TOP w0.102: U14.D2 v1(45.77,39.65) ; v1(62.73,43.28) 62.84,43.28 63.14,43.58 63.61,43.58 63.7,43.67 U15.J7
  LYR4 w0.102: v1(45.77,39.65) 46.19,39.23 47.39,39.23 47.63,38.99 51.24,38.99 52,39.75 53.01,39.75 53.14,39.62 53.14,39.32 53.39,39.07 54.25,39.07 54.53,39.35 54.53,39.68 54.61,39.75 55.25,39.75 55.32,39.68 55.32,39.37 55.58,39.11 56.26,39.11 56.81,39.66 57.13,39.66 57.43,39.36 58.03,39.36 58.42,39.75 59.18,39.75 59.69,40.26 60.43,40.26 60.79,40.62 60.79,42.96 60.95,43.12 61.16,43.12 61.31,42.97 61.31,42.65 61.62,42.34 62.13,42.34 62.41,42.62 62.41,42.95 62.73,43.28 v1(62.73,43.28)
  BOTTOM w0.102: v1(62.73,43.28) 62.25,43.76 58.66,43.76 58.27,44.16 57.51,44.16 57.4,44.26 R179.1
DDR_CLKN: length 30.7
  TOP w0.102: U14.D1 v1(46.57,39.65) ; v1(62.12,43.29) 62,43.41 61.81,43.41 61.64,43.24 61.64,43.05 61.79,42.9 62.89,42.9 63.24,43.25 U15.K7
  LYR4 w0.102: v1(62.12,43.29) 62.1,43.27 62.1,42.75 62,42.65 61.74,42.65 61.61,42.78 61.61,43.1 61.28,43.42 60.82,43.42 60.48,43.08 60.48,40.75 60.3,40.56 59.56,40.56 59.06,40.06 58.29,40.06 57.91,39.67 57.55,39.67 57.26,39.97 56.68,39.97 56.14,39.42 55.7,39.42 55.63,39.5 55.63,39.8 55.37,40.06 54.48,40.06 54.23,39.8 54.23,39.47 54.13,39.37 53.52,39.37 53.44,39.45 53.44,39.75 53.14,40.06 51.88,40.06 51.12,39.29 47.75,39.29 47.51,39.54 46.68,39.54 v1(46.57,39.65)
  BOTTOM w0.102: R182.1 57.4,43.7 57.56,43.85 58.14,43.85 58.53,43.46 61.95,43.46 v1(62.12,43.29)
DDR_CSN: length 31.7
  TOP w0.121: U15.L2 59.38,42.45 59.04,42.11 58.73,42.11 v1(58.11,42.74) ; U14.H2 v1(45.77,42.85)
  LYR4 w0.127: v1(58.11,42.74) 58.56,42.74 58.7,42.88 58.7,43.26 58.45,43.51 58.45,43.73 58.7,43.98 58.7,44.12 58.42,44.39 57.59,44.39 57.45,44.25 57.45,44.08 57.56,43.97 57.89,43.97 57.96,43.89 57.96,43.75 57.76,43.54 57.2,43.54 57.08,43.66 57.08,44.01 56.95,44.15 54.04,44.15 53.23,43.34 52.52,43.34 52.38,43.2 52.38,42.84 52.32,42.77 52.03,42.77 51.92,42.88 51.92,43.29 51.86,43.36 51.64,43.36 51.56,43.28 51.56,42.87 51.46,42.77 51.23,42.77 51.17,42.83 51.17,43.28 51.09,43.36 50.87,43.36 50.79,43.27 50.79,42.95 50.63,42.79 50.47,42.79 50.32,42.94 50.32,43.03 50.2,43.16 50.05,43.16 49.92,43.03 49.92,42.56 49.83,42.47 49.44,42.47 49.37,42.54 49.37,42.84 49.26,42.95 49.11,42.95 48.99,42.84 48.99,42.54 48.87,42.42 48.6,42.42 48.53,42.49 48.53,42.93 48.44,43.01 47.8,43.01 47.6,42.81 47.6,42.6 47.45,42.44 46.2,42.44 45.8,42.85 v1(45.77,42.85)
  BOTTOM w0.121: RP3.1 57.69,37.07 57.79,37.17 57.79,39.38 58.26,39.84 58.26,42.59 v1(58.11,42.74)
DDR_D0: length 25
  TOP w0.121: v1(44.97,46.85) U14.M3 ; U15.H7 62.45,44.85 v1(62.38,44.92)
  LYR3 w0.127: v1(62.38,44.92) 62.35,44.95 62.35,45.54 62.54,45.73 63.49,45.73 63.72,45.51 63.72,45.08 63.21,44.58 62.66,44.58 62.51,44.43 62.21,44.43 62.07,44.58 61.32,44.58 61.2,44.46 60.65,44.46 60.27,44.84 58.35,44.84 58.06,45.14 48.61,45.14 48.48,45.27 47.45,45.27 47.06,45.66 45.61,45.66 45.36,45.9 45.36,46.21 44.97,46.61 v1(44.97,46.85)
DDR_D1: length 25.2
  TOP w0.121: U15.F8 v1(64.9,46.05) ; v1(44.17,46.85) U14.M4
  LYR3 w0.127: v1(44.17,46.85) 44.57,46.45 44.57,45.89 44.81,45.66 45.12,45.66 45.36,45.41 45.36,45.1 45.61,44.86 46.68,44.86 47.03,44.51 47.39,44.51 47.92,45.04 48.38,45.04 48.52,44.91 48.67,44.76 57.58,44.76 57.78,44.55 58.64,44.55 59.14,44.06 61.05,44.06 61.36,43.75 61.7,43.75 62.01,44.06 62.46,44.06 62.7,44.29 63.34,44.29 64.49,45.44 64.49,45.64 v1(64.9,46.05)
DDR_D2: length 24.9
  TOP w0.121: U14.N1 v1(46.57,47.65) ; U15.G2 v1(60.1,46.05)
  LYR3 w0.127: v1(60.1,46.05) 59.39,46.77 59.16,46.77 58.16,47.77 57.85,47.77 57.73,47.88 53.53,47.88 53.41,47.77 53.41,47.37 53.3,47.26 53.14,47.26 53.03,47.37 53.03,47.77 52.92,47.88 52.76,47.88 52.65,47.77 52.65,47.37 52.54,47.26 52.38,47.26 52.27,47.37 52.27,47.77 52.16,47.88 52,47.88 51.89,47.77 51.89,47.37 51.78,47.26 51.62,47.26 51.51,47.37 51.51,47.77 51.4,47.88 51.24,47.88 51.13,47.77 51.13,47.37 51.02,47.26 50.86,47.26 50.75,47.37 50.75,47.77 50.64,47.88 50.23,47.88 50.12,47.77 50.12,47.36 50.02,47.26 49.82,47.26 49.71,47.37 49.71,48.27 49.58,48.39 49.33,48.39 49.22,48.28 49.22,47.47 49.11,47.36 48.95,47.36 48.84,47.47 48.84,48.28 48.73,48.39 48.57,48.39 48.46,48.28 48.46,47.47 48.35,47.36 48.19,47.36 48.08,47.47 48.08,48.28 47.97,48.39 47.74,48.39 47.51,48.16 47.51,47.78 47.39,47.65 v1(46.57,47.65)
DDR_D3: length 24.8
  TOP w0.121: U14.N2 v1(45.77,47.65) ; U15.F2 v1(59.3,46.05)
  LYR3 w0.127: v1(45.77,47.65) 45.85,47.65 46.25,47.26 46.9,47.26 47.43,46.73 48.78,46.73 48.89,46.62 48.89,46.16 49,46.05 49.16,46.05 49.27,46.16 49.27,46.62 49.38,46.73 49.54,46.73 49.65,46.62 49.65,46.16 49.76,46.05 49.92,46.05 50.03,46.16 50.03,46.62 50.15,46.73 53.66,46.73 53.89,46.95 53.89,47.37 54,47.48 54.16,47.48 54.27,47.37 54.27,46.95 54.38,46.84 54.54,46.84 54.65,46.95 54.65,47.37 54.76,47.48 54.92,47.48 55.03,47.37 55.03,46.95 55.14,46.84 55.3,46.84 55.41,46.95 55.41,47.37 55.52,47.48 55.68,47.48 55.79,47.37 55.79,46.82 55.9,46.71 56.01,46.71 56.06,46.71 56.17,46.82 56.17,47.37 56.28,47.48 56.44,47.48 56.55,47.37 56.55,46.74 56.67,46.63 56.94,46.63 57.01,46.7 57.01,47.19 57.16,47.33 58.1,47.33 58.8,46.63 58.8,45.62 59.04,45.38 59.42,45.38 59.6,45.56 59.6,45.76 v1(59.3,46.05)
DDR_D4: length 24.9
  TOP w0.121: U14.N3 v1(44.97,47.65) ; U15.H3 v1(61.04,44.85)
  LYR3 w0.127: v1(44.97,47.65) 44.97,47.98 44.89,48.06 44.65,48.06 44.56,47.97 44.56,47.45 44.56,47.45 44.77,47.24 45.13,47.24 45.36,47.01 45.36,46.7 45.61,46.46 46.93,46.46 47.47,45.91 48.23,45.91 48.62,45.52 50.72,45.52 50.83,45.63 50.83,45.99 50.95,46.1 51.1,46.1 51.22,45.99 51.22,45.63 51.33,45.52 51.48,45.52 51.6,45.63 51.6,45.99 51.71,46.1 51.87,46.1 51.98,45.99 51.98,45.63 52.09,45.52 52.25,45.52 52.36,45.63 52.36,45.99 52.47,46.1 52.63,46.1 52.74,45.99 52.74,45.63 52.85,45.52 53.01,45.52 53.12,45.63 53.12,45.99 53.23,46.1 53.39,46.1 53.5,45.99 53.5,45.63 53.61,45.52 53.77,45.52 53.88,45.63 53.88,45.99 53.99,46.1 54.15,46.1 54.26,45.99 54.26,45.63 54.37,45.52 58.02,45.52 58.46,45.07 59.8,45.07 60.07,45.34 60.55,45.34 v1(61.04,44.85)
DDR_D5: length 25
  TOP w0.121: U14.N4 v1(44.17,47.65) ; U15.H8 64.1,44.45 63.41,44.45 v1(62.86,43.9)
  LYR3 w0.127: v1(62.86,43.9) 62.76,43.8 62.07,43.8 61.8,43.52 61.26,43.52 60.99,43.8 58.8,43.8 58.39,44.2 58.34,44.2 58.33,44.22 48.35,44.22 48.25,44.11 45.54,44.11 44.56,45.09 44.56,45.41 44.32,45.66 44.01,45.66 43.78,45.89 43.78,47.26 v1(44.17,47.65)
DDR_D6: length 24.9
  TOP w0.121: v1(61.98,48.02) 61.22,47.25 U15.E3 ; U14.P3 v1(44.97,48.45)
  LYR3 w0.127: v1(61.98,48.02) 61.98,48.29 61.82,48.46 61.62,48.46 59.47,50.61 58.71,50.61 58.53,50.79 57.19,50.79 56.97,50.57 51.56,50.57 51.43,50.44 51.43,49.7 51.33,49.6 51.16,49.6 51.05,49.71 51.05,50.44 50.94,50.55 48.88,50.55 48.76,50.66 48.76,50.93 48.65,51.04 48.49,51.04 48.38,50.93 48.38,50.66 48.27,50.55 48.14,50.55 48.03,50.45 48.03,50.09 47.92,49.97 47.76,49.97 47.65,50.09 47.65,50.44 47.54,50.55 47.31,50.55 45.2,48.45 v1(44.97,48.45)
DDR_D7: length 24.8
  TOP w0.121: v1(62.3,47.32) 63.17,46.45 U15.F7 ; U14.P4 v1(44.17,48.45)
  LYR3 w0.127: v1(44.17,48.45) 44.58,48.86 45.13,48.86 47.8,51.52 59.85,51.52 60.11,51.26 60.11,50.85 60.92,50.04 61.31,50.04 62.38,48.98 62.38,47.4 v1(62.3,47.32)
DDR_D8: length 24.9
  TOP w0.121: U15.C3 v1(61.78,48.85) ; v1(48.08,44.5) 48.08,44.5 47.36,43.78 46.44,43.78 U14.J1
  LYR4 w0.127: v1(48.08,44.5) 48.25,44.5 49.31,45.56 51.65,45.56 52.29,46.2 54.85,46.2 55.43,46.77 57,46.77 57.49,47.27 58.16,47.27 58.35,47.08 60.51,47.08 60.66,47.22 60.66,47.63 60.78,47.76 61.22,47.76 61.33,47.64 61.33,47.24 61.46,47.12 61.95,47.12 62.14,46.93 62.14,46.79 62.35,46.57 63.07,46.57 63.26,46.77 63.26,46.89 63.46,47.09 63.46,47.46 63.26,47.66 62.73,47.66 62.5,47.89 62.5,48.7 62.35,48.85 v1(61.78,48.85)
DDR_D9: length 24.8
  TOP w0.121: U14.K1 v1(46.57,45.25) ; U15.C2 v1(60.1,49.25)
  LYR4 w0.127: v1(46.57,45.25) 46.62,45.3 47.88,45.3 49.16,46.58 49.16,47.59 49.31,47.74 49.43,47.74 49.67,47.74 49.78,47.63 49.78,46.69 49.89,46.58 50.15,46.58 50.26,46.69 50.26,47.63 50.37,47.74 50.61,47.74 50.72,47.63 50.72,46.69 50.82,46.59 51.07,46.59 51.19,46.71 51.19,47.58 51.64,48.03 57.58,48.03 57.85,47.77 58.17,47.77 58.46,48.05 58.46,49.18 58.57,49.3 58.79,49.3 58.91,49.18 58.91,48.72 59.08,48.55 59.33,48.55 59.56,48.79 60,48.79 60.23,48.55 60.69,48.55 60.95,48.82 60.95,49.11 60.81,49.25 v1(60.1,49.25)
DDR_D10: length 25
  TOP w0.121: U14.K2 v1(45.77,45.25) ; U15.D7 v1(63,48.05)
  LYR4 w0.127: v1(45.77,45.25) 45.77,44.97 46.65,44.1 48.51,44.1 49.15,44.73 49.15,44.75 49.46,45.06 52,45.06 52.76,45.82 55.25,45.82 55.44,46.01 55.44,46.23 55.6,46.39 55.87,46.39 56.1,46.16 56.1,45.97 56.26,45.81 56.77,45.81 56.93,45.97 56.93,46.19 57.02,46.28 57.62,46.28 58.09,46.75 61.61,46.75 61.86,46.5 61.86,46.15 62.07,45.94 63.37,45.94 63.65,46.22 63.65,46.95 63.8,47.11 63.8,47.84 63.6,48.05 v1(63,48.05)
DDR_D11: length 25.2
  TOP w0.121: U15.C8 v1(64.1,48.45) ; v1(44.97,45.25) U14.K3
  LYR4 w0.127: v1(44.97,45.25) 46.36,43.86 48.8,43.86 49.62,44.68 52.15,44.68 52.91,45.43 58.11,45.43 58.19,45.35 58.7,45.35 59,45.66 60.73,45.66 61.02,45.37 64.1,45.37 64.5,45.77 64.5,48.06 v1(64.1,48.45)
DDR_D12: length 25.2
  TOP w0.121: U14.K4 v1(44.17,45.25) ; U15.A3 v1(60.5,51.02)
  LYR4 w0.127: v1(44.17,45.25) 44.57,45.65 44.57,47.81 44.81,48.04 46.94,48.04 47.22,48.33 47.22,49.03 48.72,50.52 49.76,50.52 50.18,50.95 50.18,51.39 50.59,51.79 61.47,51.79 61.8,51.46 61.8,51.11 61.7,51.02 v1(60.5,51.02)
